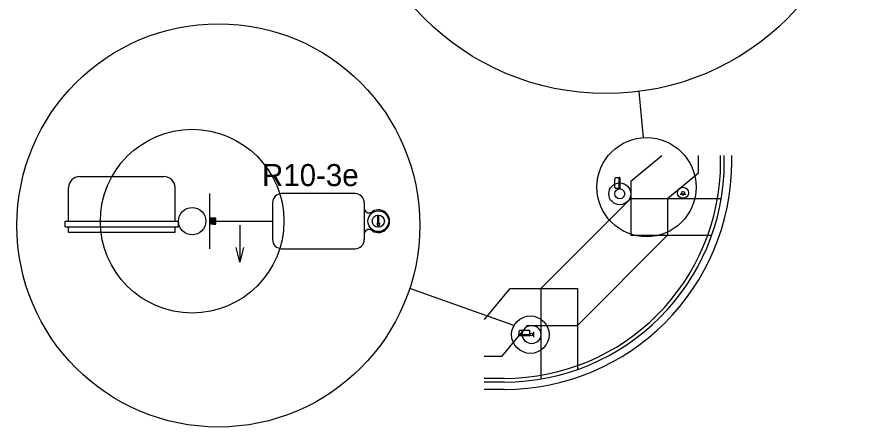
# Model space of a CAD drawing. Extents: x 418532 to 420296, y -565948 to -565286.
# Drawn here: x 419396.1 to 419569, y -565793.2 to -565709.5 of the extents above; entities that cross this region are included whole.
import ezdxf

# ---------------------------------------------------------------- set-up
doc = ezdxf.new("R2010")
doc.units = 0
doc.layers.add('T_Drafting', color=7, linetype='Continuous')

msp = doc.modelspace()

# ---------------------------------------------------------------- linework, layer by layer
at = {"layer": 'T_Drafting'}
for p, q in [((419524.18, -565734.1), (419523.28, -565724.66)), ((419521.59, -565742.94), (419527.89, -565737.76)), ((419535.42, -565741.28), (419535.42, -565737.76)), ((419539.92, -565738.98), (419539.92, -565737.76)), ((419540.67, -565738.98), (419540.67, -565737.76)), ((419542.17, -565738.98), (419542.17, -565737.76)), ((419408.93, -565742.02), (419426.18, -565742.02)), ((419519.2, -565744.56), (419519.2, -565742.24)), ((419519.31, -565742.24), (419519.2, -565742.24)), ((419519.31, -565744.56), (419519.31, -565742.24)), ((419529.09, -565746.48), (419535.42, -565741.28)), ((419518.29, -565744.26), (419518.29, -565742.54)), ((419519.2, -565742.31), (419518.51, -565742.31)), ((419519.42, -565742.31), (419519.31, -565742.31)), ((419519.42, -565744.49), (419519.42, -565742.31)), ((419521.59, -565742.94), (419521.59, -565753.98)), ((419406.68, -565751.14), (419406.68, -565744.27)), ((419428.43, -565751.14), (419428.43, -565744.27)), ((419435.49, -565745.52), (419435.49, -565756.77)), ((419465.24, -565745.52), (419450.22, -565745.52)), ((419519.2, -565744.49), (419518.51, -565744.49)), ((419519.31, -565744.56), (419519.2, -565744.56)), ((419519.42, -565744.49), (419519.31, -565744.49)), ((419448.35, -565747.39), (419448.35, -565754.89)), ((419467.12, -565754.89), (419467.12, -565747.39)), ((419521.59, -565746.48), (419503.17, -565764.91)), ((419521.59, -565746.48), (419540.04, -565746.48)), ((419529.09, -565746.48), (419529.09, -565753.98)), ((419532.8, -565745.71), (419531.67, -565745.71)), ((419532.17, -565745.84), (419532.17, -565745.71)), ((419532.17, -565745.84), (419532.3, -565745.71)), ((419532.17, -565745.84), (419532.29, -565745.71)), ((419532.17, -565745.83), (419532.29, -565745.71)), ((419532.17, -565745.83), (419532.29, -565745.71)), ((419532.17, -565745.83), (419532.29, -565745.71)), ((419532.17, -565745.83), (419532.28, -565745.71)), ((419532.17, -565745.83), (419532.28, -565745.71)), ((419532.17, -565745.82), (419532.28, -565745.71)), ((419532.17, -565745.82), (419532.28, -565745.71)), ((419532.17, -565745.82), (419532.28, -565745.71)), ((419532.17, -565745.82), (419532.27, -565745.71)), ((419532.17, -565745.82), (419532.27, -565745.71)), ((419532.17, -565745.81), (419532.27, -565745.71)), ((419532.17, -565745.81), (419532.27, -565745.71)), ((419532.17, -565745.81), (419532.27, -565745.71)), ((419532.17, -565745.81), (419532.26, -565745.71)), ((419532.17, -565745.8), (419532.26, -565745.71)), ((419532.17, -565745.8), (419532.26, -565745.71)), ((419532.17, -565745.8), (419532.26, -565745.71)), ((419532.17, -565745.8), (419532.25, -565745.71)), ((419532.17, -565745.8), (419532.25, -565745.71)), ((419532.17, -565745.79), (419532.25, -565745.71)), ((419532.17, -565745.79), (419532.25, -565745.71)), ((419532.17, -565745.79), (419532.25, -565745.71)), ((419532.17, -565745.79), (419532.24, -565745.71)), ((419532.17, -565745.79), (419532.24, -565745.71)), ((419532.17, -565745.78), (419532.24, -565745.71)), ((419532.17, -565745.78), (419532.24, -565745.71)), ((419532.17, -565745.78), (419532.24, -565745.71)), ((419532.17, -565745.78), (419532.23, -565745.71)), ((419532.17, -565745.78), (419532.23, -565745.71)), ((419532.17, -565745.77), (419532.23, -565745.71)), ((419532.17, -565745.77), (419532.23, -565745.71)), ((419532.17, -565745.77), (419532.23, -565745.71)), ((419532.17, -565745.77), (419532.22, -565745.71)), ((419532.17, -565745.76), (419532.22, -565745.71)), ((419532.17, -565745.76), (419532.22, -565745.71)), ((419532.17, -565745.76), (419532.22, -565745.71)), ((419532.17, -565745.76), (419532.21, -565745.71)), ((419532.17, -565745.76), (419532.21, -565745.71)), ((419532.17, -565745.75), (419532.21, -565745.71)), ((419532.17, -565745.75), (419532.21, -565745.71)), ((419532.17, -565745.75), (419532.21, -565745.71)), ((419532.17, -565745.75), (419532.2, -565745.71)), ((419532.17, -565745.75), (419532.2, -565745.71)), ((419532.17, -565745.74), (419532.2, -565745.71)), ((419532.17, -565745.74), (419532.2, -565745.71)), ((419532.17, -565745.74), (419532.2, -565745.71)), ((419532.17, -565745.74), (419532.19, -565745.71)), ((419532.17, -565745.73), (419532.19, -565745.71)), ((419532.17, -565745.73), (419532.19, -565745.71)), ((419532.17, -565745.73), (419532.19, -565745.71)), ((419532.17, -565745.73), (419532.18, -565745.71)), ((419532.17, -565745.73), (419532.18, -565745.71)), ((419532.17, -565745.72), (419532.18, -565745.71)), ((419532.17, -565745.72), (419532.18, -565745.71)), ((419532.17, -565745.72), (419532.18, -565745.71)), ((419532.17, -565745.72), (419532.17, -565745.71)), ((419532.17, -565745.72), (419532.17, -565745.71)), ((419532.17, -565745.84), (419532.3, -565745.72)), ((419532.17, -565745.84), (419532.3, -565745.72)), ((419532.17, -565745.84), (419532.3, -565745.84)), ((419532.18, -565745.84), (419532.3, -565745.72)), ((419532.18, -565745.84), (419532.3, -565745.72)), ((419532.18, -565745.84), (419532.3, -565745.72)), ((419532.18, -565745.84), (419532.3, -565745.73)), ((419532.19, -565745.84), (419532.3, -565745.73)), ((419532.19, -565745.84), (419532.3, -565745.73)), ((419532.19, -565745.84), (419532.3, -565745.73)), ((419532.19, -565745.84), (419532.3, -565745.74)), ((419532.19, -565745.84), (419532.3, -565745.74)), ((419532.2, -565745.84), (419532.3, -565745.74)), ((419532.2, -565745.84), (419532.3, -565745.74)), ((419532.2, -565745.84), (419532.3, -565745.74)), ((419532.2, -565745.84), (419532.3, -565745.75)), ((419532.2, -565745.84), (419532.3, -565745.75)), ((419532.21, -565745.84), (419532.3, -565745.75)), ((419532.21, -565745.84), (419532.3, -565745.75)), ((419532.21, -565745.84), (419532.3, -565745.75)), ((419532.21, -565745.84), (419532.3, -565745.76)), ((419532.21, -565745.84), (419532.3, -565745.76)), ((419532.22, -565745.84), (419532.3, -565745.76)), ((419532.22, -565745.84), (419532.3, -565745.76)), ((419532.22, -565745.84), (419532.3, -565745.76)), ((419532.22, -565745.84), (419532.3, -565745.77)), ((419532.23, -565745.84), (419532.3, -565745.77)), ((419532.23, -565745.84), (419532.3, -565745.77)), ((419532.23, -565745.84), (419532.3, -565745.77)), ((419532.23, -565745.84), (419532.3, -565745.78)), ((419532.23, -565745.84), (419532.3, -565745.78)), ((419532.24, -565745.84), (419532.3, -565745.78)), ((419532.24, -565745.84), (419532.3, -565745.78)), ((419532.24, -565745.84), (419532.3, -565745.78)), ((419532.24, -565745.84), (419532.3, -565745.79)), ((419532.24, -565745.84), (419532.3, -565745.79)), ((419532.25, -565745.84), (419532.3, -565745.79)), ((419532.25, -565745.84), (419532.3, -565745.79)), ((419532.25, -565745.84), (419532.3, -565745.79)), ((419532.25, -565745.84), (419532.3, -565745.8)), ((419532.26, -565745.84), (419532.3, -565745.8)), ((419532.26, -565745.84), (419532.3, -565745.8)), ((419532.26, -565745.84), (419532.3, -565745.8)), ((419532.26, -565745.84), (419532.3, -565745.81)), ((419532.26, -565745.84), (419532.3, -565745.81)), ((419532.27, -565745.84), (419532.3, -565745.81)), ((419532.27, -565745.84), (419532.3, -565745.81)), ((419532.27, -565745.84), (419532.3, -565745.81)), ((419532.27, -565745.84), (419532.3, -565745.82)), ((419532.27, -565745.84), (419532.3, -565745.82)), ((419532.28, -565745.84), (419532.3, -565745.82)), ((419532.28, -565745.84), (419532.3, -565745.82)), ((419532.28, -565745.84), (419532.3, -565745.82)), ((419532.28, -565745.84), (419532.3, -565745.83)), ((419532.28, -565745.84), (419532.3, -565745.83)), ((419532.29, -565745.84), (419532.3, -565745.83)), ((419532.29, -565745.84), (419532.3, -565745.83)), ((419532.29, -565745.84), (419532.3, -565745.83)), ((419532.29, -565745.84), (419532.3, -565745.84)), ((419532.3, -565745.84), (419532.3, -565745.71)), ((419532.3, -565745.84), (419532.3, -565745.84)), ((419436.74, -565750.52), (419435.49, -565750.52)), ((419435.49, -565751.76), (419436.74, -565750.52)), ((419435.49, -565751.74), (419436.72, -565750.52)), ((419435.49, -565751.72), (419436.7, -565750.52)), ((419435.49, -565751.7), (419436.67, -565750.52)), ((419435.49, -565751.68), (419436.65, -565750.52)), ((419435.49, -565751.66), (419436.63, -565750.52)), ((419435.49, -565751.63), (419436.61, -565750.52)), ((419435.49, -565751.61), (419436.59, -565750.52)), ((419435.49, -565751.59), (419436.57, -565750.52)), ((419435.49, -565751.57), (419436.55, -565750.52)), ((419435.49, -565751.55), (419436.53, -565750.52)), ((419435.49, -565751.53), (419436.5, -565750.52)), ((419435.49, -565751.51), (419436.48, -565750.52)), ((419435.49, -565751.49), (419436.46, -565750.52)), ((419435.49, -565751.46), (419436.44, -565750.52)), ((419435.49, -565751.44), (419436.42, -565750.52)), ((419435.49, -565751.42), (419436.4, -565750.52)), ((419435.49, -565751.4), (419436.38, -565750.52)), ((419435.49, -565751.38), (419436.36, -565750.52)), ((419435.49, -565751.36), (419436.33, -565750.52)), ((419435.49, -565751.34), (419436.31, -565750.52)), ((419435.49, -565751.32), (419436.29, -565750.52)), ((419435.49, -565751.29), (419436.27, -565750.52)), ((419435.49, -565751.27), (419436.25, -565750.52)), ((419435.49, -565751.25), (419436.23, -565750.52)), ((419435.49, -565751.23), (419436.21, -565750.52)), ((419435.49, -565751.21), (419436.19, -565750.52)), ((419435.49, -565751.19), (419436.16, -565750.52)), ((419435.49, -565751.17), (419436.14, -565750.52)), ((419435.49, -565751.15), (419436.12, -565750.52)), ((419435.49, -565751.12), (419436.1, -565750.52)), ((419435.49, -565751.1), (419436.08, -565750.52)), ((419435.49, -565751.08), (419436.06, -565750.52)), ((419435.49, -565751.06), (419436.04, -565750.52)), ((419435.49, -565751.04), (419436.02, -565750.52)), ((419435.49, -565751.02), (419436, -565750.52)), ((419435.49, -565751), (419435.97, -565750.52)), ((419435.49, -565750.98), (419435.95, -565750.52)), ((419435.49, -565750.96), (419435.93, -565750.52)), ((419435.49, -565750.93), (419435.91, -565750.52)), ((419435.49, -565750.91), (419435.89, -565750.52)), ((419435.49, -565750.89), (419435.87, -565750.52)), ((419435.49, -565750.87), (419435.85, -565750.52)), ((419435.49, -565750.85), (419435.83, -565750.52)), ((419435.49, -565750.83), (419435.8, -565750.52)), ((419435.49, -565750.81), (419435.78, -565750.52)), ((419435.49, -565750.79), (419435.76, -565750.52)), ((419435.49, -565750.76), (419435.74, -565750.52)), ((419435.49, -565750.74), (419435.72, -565750.52)), ((419435.49, -565750.72), (419435.7, -565750.52)), ((419435.49, -565750.7), (419435.68, -565750.52)), ((419435.49, -565750.68), (419435.66, -565750.52)), ((419435.49, -565750.66), (419435.63, -565750.52)), ((419435.49, -565750.64), (419435.61, -565750.52)), ((419435.49, -565750.62), (419435.59, -565750.52)), ((419435.49, -565750.59), (419435.57, -565750.52)), ((419435.49, -565750.57), (419435.55, -565750.52)), ((419435.49, -565750.55), (419435.53, -565750.52)), ((419435.49, -565750.53), (419435.51, -565750.52)), ((419435.51, -565751.77), (419436.74, -565750.53)), ((419435.53, -565751.77), (419436.74, -565750.55)), ((419435.55, -565751.77), (419436.74, -565750.57)), ((419435.57, -565751.77), (419436.74, -565750.6)), ((419435.59, -565751.77), (419436.74, -565750.62)), ((419435.61, -565751.77), (419436.74, -565750.64)), ((419435.64, -565751.77), (419436.74, -565750.66)), ((419435.66, -565751.77), (419436.74, -565750.68)), ((419435.68, -565751.77), (419436.74, -565750.7)), ((419435.7, -565751.77), (419436.74, -565750.72)), ((419435.72, -565751.77), (419436.74, -565750.74)), ((419435.74, -565751.77), (419436.74, -565750.77)), ((419435.76, -565751.77), (419436.74, -565750.79)), ((419435.78, -565751.77), (419436.74, -565750.81)), ((419435.81, -565751.77), (419436.74, -565750.83)), ((419435.83, -565751.77), (419436.74, -565750.85)), ((419435.85, -565751.77), (419436.74, -565750.87)), ((419435.87, -565751.77), (419436.74, -565750.89)), ((419436.74, -565751.77), (419436.74, -565750.52)), ((419469.86, -565749.9), (419470.08, -565749.9)), ((419469.86, -565751.78), (419469.86, -565749.9)), ((419470.08, -565751.78), (419470.08, -565749.9)), ((419405.99, -565751.14), (419429.12, -565751.14)), ((419405.99, -565752.27), (419405.99, -565751.14)), ((419405.99, -565752.27), (419429.12, -565752.27)), ((419406.68, -565753.39), (419406.68, -565752.27)), ((419428.43, -565753.39), (419428.43, -565752.27)), ((419429.12, -565752.27), (419429.12, -565751.14)), ((419436.74, -565751.77), (419435.49, -565751.77)), ((419435.89, -565751.77), (419436.74, -565750.91)), ((419435.91, -565751.77), (419436.74, -565750.94)), ((419435.93, -565751.77), (419436.74, -565750.96)), ((419435.95, -565751.77), (419436.74, -565750.98)), ((419435.98, -565751.77), (419436.74, -565751)), ((419436, -565751.77), (419436.74, -565751.02)), ((419436.02, -565751.77), (419436.74, -565751.04)), ((419436.04, -565751.77), (419436.74, -565751.06)), ((419436.06, -565751.77), (419436.74, -565751.08)), ((419436.08, -565751.77), (419436.74, -565751.11)), ((419436.1, -565751.77), (419436.74, -565751.13)), ((419436.12, -565751.77), (419436.74, -565751.15)), ((419436.15, -565751.77), (419436.74, -565751.17)), ((419436.17, -565751.77), (419436.74, -565751.19)), ((419436.19, -565751.77), (419436.74, -565751.21)), ((419436.21, -565751.77), (419436.74, -565751.23)), ((419436.23, -565751.77), (419436.74, -565751.25)), ((419436.25, -565751.77), (419436.74, -565751.27)), ((419436.27, -565751.77), (419436.74, -565751.3)), ((419436.29, -565751.77), (419436.74, -565751.32)), ((419436.31, -565751.77), (419436.74, -565751.34)), ((419436.34, -565751.77), (419436.74, -565751.36)), ((419436.36, -565751.77), (419436.74, -565751.38)), ((419436.38, -565751.77), (419436.74, -565751.4)), ((419436.4, -565751.77), (419436.74, -565751.42)), ((419436.42, -565751.77), (419436.74, -565751.44)), ((419436.44, -565751.77), (419436.74, -565751.47)), ((419436.46, -565751.77), (419436.74, -565751.49)), ((419436.48, -565751.77), (419436.74, -565751.51)), ((419436.51, -565751.77), (419436.74, -565751.53)), ((419436.53, -565751.77), (419436.74, -565751.55)), ((419436.55, -565751.77), (419436.74, -565751.57)), ((419436.57, -565751.77), (419436.74, -565751.59)), ((419436.59, -565751.77), (419436.74, -565751.61)), ((419436.61, -565751.77), (419436.74, -565751.64)), ((419436.63, -565751.77), (419436.74, -565751.66)), ((419436.65, -565751.77), (419436.74, -565751.68)), ((419436.68, -565751.77), (419436.74, -565751.7)), ((419436.7, -565751.77), (419436.74, -565751.72)), ((419436.72, -565751.77), (419436.74, -565751.74)), ((419436.74, -565751.14), (419448.35, -565751.14)), ((419436.74, -565751.77), (419436.74, -565751.76)), ((419441.66, -565751.94), (419441.66, -565759.49)), ((419469.67, -565751.63), (419469.97, -565752.39)), ((419469.86, -565751.78), (419469.67, -565751.63)), ((419470.27, -565751.63), (419469.97, -565752.39)), ((419470.27, -565751.63), (419470.08, -565751.78)), ((419406.68, -565753.39), (419428.43, -565753.39)), ((419529.09, -565753.98), (419510.67, -565772.41)), ((419521.59, -565753.98), (419538.09, -565753.98)), ((419450.22, -565756.77), (419465.24, -565756.77)), ((419497.68, -565772.45), (419476.4, -565764.87)), ((419496.83, -565764.91), (419491.63, -565771.23)), ((419496.83, -565764.91), (419510.67, -565764.91)), ((419503.17, -565764.91), (419503.17, -565783.35)), ((419510.67, -565764.91), (419510.67, -565781.41)), ((419500.37, -565772.41), (419495.17, -565778.73)), ((419498.99, -565773.37), (419500.72, -565773.37)), ((419500.37, -565772.41), (419510.67, -565772.41)), ((419498.7, -565774.28), (419501.01, -565774.28)), ((419498.7, -565774.4), (419498.7, -565774.28)), ((419498.7, -565774.4), (419501.01, -565774.4)), ((419498.77, -565774.28), (419498.77, -565773.6)), ((419498.77, -565774.51), (419498.77, -565774.4)), ((419498.77, -565774.51), (419500.94, -565774.51)), ((419500.94, -565774.28), (419500.94, -565773.6)), ((419500.94, -565774.51), (419500.94, -565774.4)), ((419501.01, -565774.4), (419501.01, -565774.28)), ((419501.65, -565773.72), (419501.65, -565774.85)), ((419501.77, -565774.22), (419501.65, -565774.22)), ((419501.65, -565774.35), (419501.77, -565774.22)), ((419501.65, -565774.35), (419501.77, -565774.22)), ((419501.65, -565774.34), (419501.77, -565774.22)), ((419501.65, -565774.34), (419501.77, -565774.22)), ((419501.65, -565774.34), (419501.77, -565774.22)), ((419501.65, -565774.34), (419501.76, -565774.22)), ((419501.65, -565774.34), (419501.76, -565774.22)), ((419501.65, -565774.33), (419501.76, -565774.22)), ((419501.65, -565774.33), (419501.76, -565774.22)), ((419501.65, -565774.33), (419501.76, -565774.22)), ((419501.65, -565774.33), (419501.75, -565774.22)), ((419501.65, -565774.33), (419501.75, -565774.22)), ((419501.65, -565774.32), (419501.75, -565774.22)), ((419501.65, -565774.32), (419501.75, -565774.22)), ((419501.65, -565774.32), (419501.74, -565774.22)), ((419501.65, -565774.32), (419501.74, -565774.22)), ((419501.65, -565774.31), (419501.74, -565774.22)), ((419501.65, -565774.31), (419501.74, -565774.22)), ((419501.65, -565774.31), (419501.74, -565774.22)), ((419501.65, -565774.31), (419501.73, -565774.22)), ((419501.65, -565774.31), (419501.73, -565774.22)), ((419501.65, -565774.3), (419501.73, -565774.22)), ((419501.65, -565774.3), (419501.73, -565774.22)), ((419501.65, -565774.3), (419501.73, -565774.22)), ((419501.65, -565774.3), (419501.72, -565774.22)), ((419501.65, -565774.3), (419501.72, -565774.22)), ((419501.65, -565774.29), (419501.72, -565774.22)), ((419501.65, -565774.29), (419501.72, -565774.22)), ((419501.65, -565774.29), (419501.71, -565774.22)), ((419501.65, -565774.29), (419501.71, -565774.22)), ((419501.65, -565774.29), (419501.71, -565774.22)), ((419501.65, -565774.28), (419501.71, -565774.22)), ((419501.65, -565774.28), (419501.71, -565774.22)), ((419501.65, -565774.28), (419501.7, -565774.22)), ((419501.65, -565774.28), (419501.7, -565774.22)), ((419501.65, -565774.27), (419501.7, -565774.22)), ((419501.65, -565774.27), (419501.7, -565774.22)), ((419501.65, -565774.27), (419501.7, -565774.22)), ((419501.65, -565774.27), (419501.69, -565774.22)), ((419501.65, -565774.27), (419501.69, -565774.22)), ((419501.65, -565774.26), (419501.69, -565774.22)), ((419501.65, -565774.26), (419501.69, -565774.22)), ((419501.65, -565774.26), (419501.69, -565774.22)), ((419501.65, -565774.26), (419501.68, -565774.22)), ((419501.65, -565774.26), (419501.68, -565774.22)), ((419501.65, -565774.25), (419501.68, -565774.22)), ((419501.65, -565774.25), (419501.68, -565774.22)), ((419501.65, -565774.25), (419501.67, -565774.22)), ((419501.65, -565774.25), (419501.67, -565774.22)), ((419501.65, -565774.24), (419501.67, -565774.22)), ((419501.65, -565774.24), (419501.67, -565774.22)), ((419501.65, -565774.24), (419501.67, -565774.22)), ((419501.65, -565774.24), (419501.66, -565774.22)), ((419501.65, -565774.24), (419501.66, -565774.22)), ((419501.65, -565774.23), (419501.66, -565774.22)), ((419501.65, -565774.23), (419501.66, -565774.22)), ((419501.65, -565774.23), (419501.66, -565774.22)), ((419501.65, -565774.23), (419501.65, -565774.22)), ((419501.65, -565774.23), (419501.65, -565774.22)), ((419501.65, -565774.22), (419501.65, -565774.22)), ((419501.65, -565774.35), (419501.77, -565774.23)), ((419501.65, -565774.35), (419501.77, -565774.23)), ((419501.77, -565774.35), (419501.65, -565774.35)), ((419501.66, -565774.35), (419501.77, -565774.23)), ((419501.66, -565774.35), (419501.77, -565774.23)), ((419501.66, -565774.35), (419501.77, -565774.23)), ((419501.66, -565774.35), (419501.77, -565774.24)), ((419501.66, -565774.35), (419501.77, -565774.24)), ((419501.67, -565774.35), (419501.77, -565774.24)), ((419501.67, -565774.35), (419501.77, -565774.24)), ((419501.67, -565774.35), (419501.77, -565774.25)), ((419501.67, -565774.35), (419501.77, -565774.25)), ((419501.67, -565774.35), (419501.77, -565774.25)), ((419501.68, -565774.35), (419501.77, -565774.25)), ((419501.68, -565774.35), (419501.77, -565774.25)), ((419501.68, -565774.35), (419501.77, -565774.26)), ((419501.68, -565774.35), (419501.77, -565774.26)), ((419501.69, -565774.35), (419501.77, -565774.26)), ((419501.69, -565774.35), (419501.77, -565774.26)), ((419501.69, -565774.35), (419501.77, -565774.26)), ((419501.69, -565774.35), (419501.77, -565774.27)), ((419501.69, -565774.35), (419501.77, -565774.27)), ((419501.7, -565774.35), (419501.77, -565774.27)), ((419501.7, -565774.35), (419501.77, -565774.27)), ((419501.7, -565774.35), (419501.77, -565774.27)), ((419501.7, -565774.35), (419501.77, -565774.28)), ((419501.7, -565774.35), (419501.77, -565774.28)), ((419501.71, -565774.35), (419501.77, -565774.28)), ((419501.71, -565774.35), (419501.77, -565774.28)), ((419501.71, -565774.35), (419501.77, -565774.29)), ((419501.71, -565774.35), (419501.77, -565774.29)), ((419501.72, -565774.35), (419501.77, -565774.29)), ((419501.72, -565774.35), (419501.77, -565774.29)), ((419501.72, -565774.35), (419501.77, -565774.29)), ((419501.72, -565774.35), (419501.77, -565774.3)), ((419501.72, -565774.35), (419501.77, -565774.3)), ((419501.73, -565774.35), (419501.77, -565774.3)), ((419501.73, -565774.35), (419501.77, -565774.3)), ((419501.73, -565774.35), (419501.77, -565774.3)), ((419501.73, -565774.35), (419501.77, -565774.31)), ((419501.73, -565774.35), (419501.77, -565774.31)), ((419501.74, -565774.35), (419501.77, -565774.31)), ((419501.74, -565774.35), (419501.77, -565774.31)), ((419501.74, -565774.35), (419501.77, -565774.32)), ((419501.74, -565774.35), (419501.77, -565774.32)), ((419501.74, -565774.35), (419501.77, -565774.32)), ((419501.75, -565774.35), (419501.77, -565774.32)), ((419501.75, -565774.35), (419501.77, -565774.32)), ((419501.75, -565774.35), (419501.77, -565774.33)), ((419501.75, -565774.35), (419501.77, -565774.33)), ((419501.76, -565774.35), (419501.77, -565774.33)), ((419501.76, -565774.35), (419501.77, -565774.33)), ((419501.76, -565774.35), (419501.77, -565774.33)), ((419501.76, -565774.35), (419501.77, -565774.34)), ((419501.76, -565774.35), (419501.77, -565774.34)), ((419501.77, -565774.35), (419501.77, -565774.22)), ((419501.77, -565774.35), (419501.77, -565774.34)), ((419501.77, -565774.35), (419501.77, -565774.34)), ((419501.77, -565774.35), (419501.77, -565774.34)), ((419501.77, -565774.35), (419501.77, -565774.35)), ((419495.17, -565778.73), (419491.63, -565778.73)), ((419495.67, -565783.23), (419491.63, -565783.23)), ((419495.67, -565783.98), (419491.63, -565783.98)), ((419495.67, -565785.48), (419491.63, -565785.48))]:
    msp.add_line(p, q, dxfattribs=at)
msp.add_lwpolyline([(419442.41, -565756.49), (419441.66, -565759.49), (419440.91, -565756.49)], dxfattribs=at)
for centre, radius in [((419516.48, -565672.56), 52.54), ((419437.29, -565752), 41.16), ((419431.93, -565751.14), 18.75), ((419524.77, -565744.2), 10.12), ((419519.31, -565745.56), 2.25), ((419519.31, -565745.56), 1), ((419532.23, -565745.35), 1.12), ((419532.23, -565745.35), 0.285), ((419431.93, -565751.14), 2.81), ((419469.97, -565751.14), 2.12), ((419469.97, -565751.14), 1.25), ((419501.03, -565774.3), 3.83), ((419501.29, -565774.28), 1.87), ((419501.29, -565774.28), 0.281)]:
    msp.add_circle(centre, radius, dxfattribs=at)
for centre, radius, start, end in [((419495.67, -565738.98), 45, 270, 0), ((419495.67, -565738.98), 46.5, 270, 0), ((419495.67, -565738.98), 44.25, 270, 0), ((419408.93, -565744.27), 2.25, 90, 180), ((419426.18, -565744.27), 2.25, 360, 90), ((419518.51, -565742.54), 0.225, 90, 180), ((419450.22, -565747.39), 1.87, 90, 180), ((419465.24, -565747.39), 1.87, 0, 90), ((419518.51, -565744.26), 0.225, 180, 270), ((419468.07, -565748.38), 1.05, 205.1956, 311.8028), ((419469.97, -565751.14), 2.31, 238.7402, 121.2598), ((419469.97, -565751.14), 2.31, 42.5066, 121.2598), ((419468.07, -565753.9), 1.05, 48.1972, 154.8044), ((419469.97, -565751.14), 2.31, 238.7402, 317.4934), ((419450.22, -565754.89), 1.87, 180, 270), ((419465.24, -565754.89), 1.87, 270, 0), ((419498.99, -565773.6), 0.225, 90, 180), ((419500.72, -565773.6), 0.225, 360, 90)]:
    msp.add_arc(centre, radius, start, end, dxfattribs=at)

# ---------------------------------------------------------------- texts
msp.add_text('R10-3e', height=4.5, dxfattribs=at).set_placement((419446.21, -565743.98))

doc.saveas('drawing.dxf')
